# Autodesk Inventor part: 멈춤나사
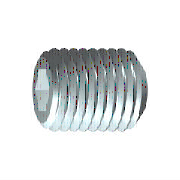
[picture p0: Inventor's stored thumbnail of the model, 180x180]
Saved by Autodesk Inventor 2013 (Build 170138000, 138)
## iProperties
IsCustomPart: 1
Company: 한국ATC센터
Created: 2009-02
Part Number: 멈춤나사
Material: 강, 연강
Description: 6각 소켓 머리 없는 멈춤 나사
Document SubType Name: Modeling
Standard: KS B 1028
Designer: KYOUNG IL JANG
Standards Organization: KS
Language: ko-KR
Size Designation: 납작점M3x6
Categories: <MemberInstance><Categories><Category DisplayName="조임쇠" InternalName="e4da775c-781d-43d5-af7c-5136215cf5a6" Mnemonic="FSTN"><Category DisplayName="볼트" InternalN
Density: 7.86 g/cm^3
Mass: 0.293227 g
Surface Area: 0.779768 cm^2
Volume: 0.0373062 cm^3
Vendor: CBT Solutions
Author: KYOUNG IL JANG
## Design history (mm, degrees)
sketch "스케치1"
  geometry: L1 (0, 0)-(3.5, 0); L2 (6, 0.866)-(6, 1.5); L3 (6, 1.5)-(0, 1.5); L4 (6, 0.866)-(4, 0.866); L5 (4, 0.866)-(3.5, 0); L6 (0, -0.3)-(0, 1.8) reference; L7 (0, 1.5)-(0, 0)
  constraints: 13 end point, 3 parallel, 1 collinear, 1 perpendicular, 1 point on line
  dimensions: "d0" = 2 distance of L2.start L4.end (= INTI); "d1" = 60 deg angle of L5 L1; "d2" = 3 diameter of L3 L1 (= NND); "d3" = 1.73205 diameter of L4 L1 (= 1.1547 x SW); "d5" = 6 distance from line of L2 L3.end (= NLG)
revolve "본체" sketch "스케치1" stored, may be unused: angle "d6" = 90 deg
sketch "스케치2"
  geometry: L1 (-0.433, 0.75)-(0.433, 0.75); L2 (0.433, 0.75)-(0.866, 0); L3 (0.866, 0)-(0.433, -0.75); L4 (0.433, -0.75)-(-0.433, -0.75); L5 (-0.433, -0.75)-(-0.866, 0); L6 (-0.866, 0)-(-0.433, 0.75); A1 r 0.866 centre (0, 0) between (-0.433, 0.75) and (0.433, 0.75) reference; 2 further points
  constraints: 12 end point, 2 point on circle, 1 coincident, 1 horizontal, 11 other
extrude "슬롯" join sketch "스케치2" taper "d9" = 0 deg; stored distance "d21" = 10
workaxis "Work Axis1"
workplane "Work Plane1"
body "Solid1"
chamfer "모따기1" distance "d7" = 0.30673 (= -0.5 x GD1 + 0.5 x NND); stored, may be unused: angle "d8" = 45 deg (= FAWI), second distance "d29" = 0.30673 (= -0.5 x GD1 + 0.5 x NND)
feature "스레드" dims "d11" = 6 (= NLG), "d12" = 0
chamfer "모따기2" distance "d13" = 0.30673 (= -0.5 x GD1 + 0.5 x NND); stored, may be unused: angle "d14" = 45 deg (= FAWI), second distance "d30" = 0.30673 (= -0.5 x GD1 + 0.5 x NND)
other parameters: "NND" = 3 [user parameter; used in 5 equation terms], "NLG" = 6 [user parameter; used in 2 equation terms], "INTI" = 2 [user parameter; used in 1 equation term], "FAWI" = 45 deg [user parameter; used in 2 equation terms], "SW" = 1.5 [user parameter; used in 2 equation terms], "GD1" = 2.38655 (= THREADDIA - 1.2269 x PTC) [user parameter; used in 4 equation terms], "d4" = 0, "FAWI1" = 45 deg [user parameter], "d15" = 0, "d31" = 0, "GUL" = 0.30673 (= 0.61345 x PTC) [user parameter], "SPD" = 2 [user parameter], "TOA" = 30 deg [user parameter], "THREADDIA" = 3 [user parameter; used in 1 equation term], "PTC" = 0.5 [user parameter; used in 4 equation terms], "GAL" = 0.30673 (= 0.61345 x PTC) [user parameter], "E0" = 1.7325 (= 1.155 x SW) [user parameter]
